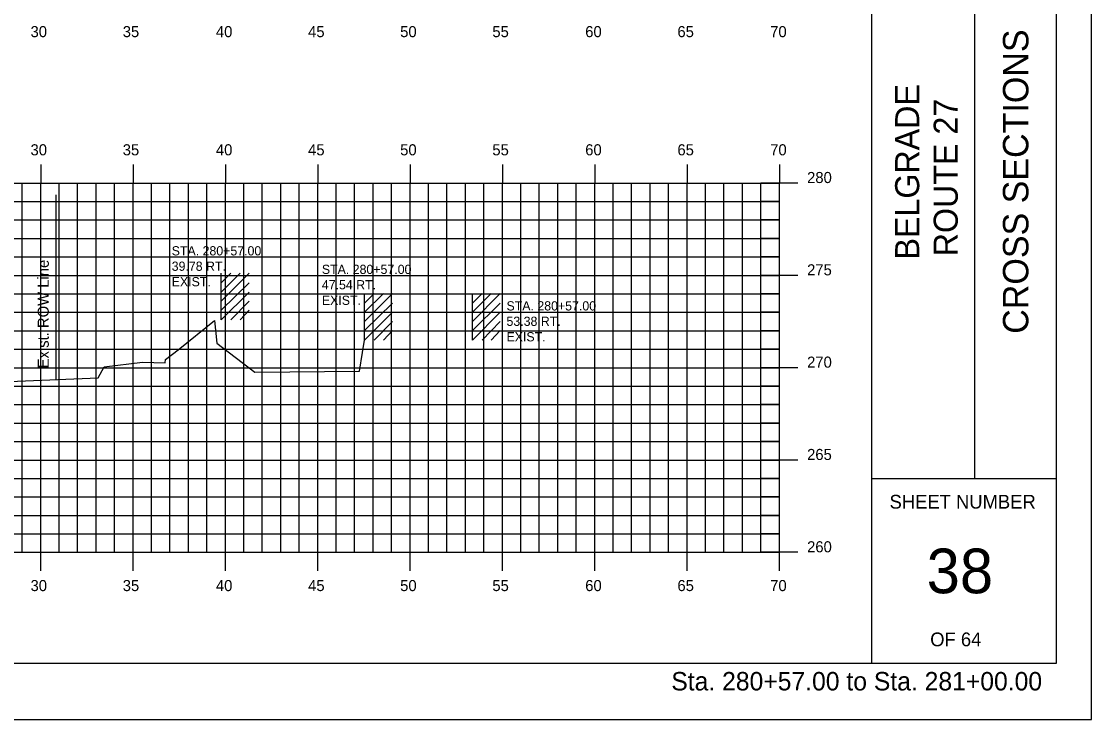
# Model space of a CAD drawing. Extents: x 855344 to 855514, y 366268 to 366378.
# Drawn here: x 855456.1 to 855514, y 366268.2 to 366306 of the extents above; entities that cross this region are included whole.
import ezdxf

# ---------------------------------------------------------------- set-up
doc = ezdxf.new("R2010")
doc.units = 0
for name, color, linetype in [('BORDER', 7, 'Continuous'), ('D_Text_Monospaced', 7, 'Continuous'), ('E_ROW_Line', 7, 'Continuous'), ('H_V ANNOTATION', 7, 'Continuous'), ('HIGHWAY_TITLE', 7, 'Continuous'), ('MAJOR', 7, 'Continuous'), ('MINOR', 7, 'Continuous'), ('PLOT BOUNDARY', 7, 'Continuous'), ('S_Buildings', 7, 'Continuous'), ('S_Buildings_Attachments', 7, 'Continuous'), ('S_Roadway_Centerline', 7, 'Continuous')]:
    doc.layers.add(name, color=color, linetype=linetype)

msp = doc.modelspace()

# ---------------------------------------------------------------- linework, layer by layer
at = {"layer": 'BORDER'}
for p, q in [((855502.11, 366271.236), (855502.11, 366376.239)), ((855512.11, 366271.236), (855512.11, 366376.236)), ((855507.701, 366281.239), (855507.701, 366316.239)), ((855502.11, 366281.239), (855512.11, 366281.239)), ((855352.11, 366271.236), (855512.11, 366271.236))]:
    msp.add_line(p, q, dxfattribs=at)
at = {"layer": 'E_ROW_Line'}
msp.add_line((855457.946, 366286.598), (855457.946, 366296.598), dxfattribs=at)
at = {"layer": 'MAJOR'}
for p, q in [((855457.11, 366298.238), (855457.11, 366297.236)), ((855462.11, 366298.238), (855462.11, 366297.236)), ((855467.11, 366298.238), (855467.11, 366297.236)), ((855472.11, 366298.238), (855472.11, 366297.236)), ((855477.11, 366298.238), (855477.11, 366297.236)), ((855482.11, 366298.238), (855482.11, 366297.236)), ((855487.11, 366298.238), (855487.11, 366297.236)), ((855492.11, 366298.238), (855492.11, 366297.236)), ((855497.11, 366298.238), (855497.11, 366297.236)), ((855357.11, 366297.236), (855497.11, 366297.236)), ((855357.11, 366297.236), (855497.11, 366297.236)), ((855457.11, 366277.236), (855457.11, 366297.236)), ((855462.11, 366277.236), (855462.11, 366297.236)), ((855467.11, 366277.236), (855467.11, 366297.236)), ((855472.11, 366277.236), (855472.11, 366297.236)), ((855477.11, 366277.236), (855477.11, 366297.236)), ((855482.11, 366277.236), (855482.11, 366297.236)), ((855487.11, 366277.236), (855487.11, 366297.236)), ((855492.11, 366277.236), (855492.11, 366297.236)), ((855498.112, 366297.236), (855496.108, 366297.236)), ((855497.11, 366277.236), (855497.11, 366297.236)), ((855497.11, 366277.236), (855497.11, 366297.236)), ((855357.11, 366292.236), (855497.11, 366292.236)), ((855498.112, 366292.236), (855496.108, 366292.236)), ((855357.11, 366287.236), (855497.11, 366287.236)), ((855498.112, 366287.236), (855496.108, 366287.236)), ((855357.11, 366282.236), (855497.11, 366282.236)), ((855498.112, 366282.236), (855496.108, 366282.236)), ((855357.11, 366277.236), (855497.11, 366277.236)), ((855357.11, 366277.236), (855497.11, 366277.236)), ((855457.11, 366276.234), (855457.11, 366277.236)), ((855462.11, 366276.234), (855462.11, 366277.236)), ((855467.11, 366276.234), (855467.11, 366277.236)), ((855472.11, 366276.234), (855472.11, 366277.236)), ((855477.11, 366276.234), (855477.11, 366277.236)), ((855482.11, 366276.234), (855482.11, 366277.236)), ((855487.11, 366276.234), (855487.11, 366277.236)), ((855492.11, 366276.234), (855492.11, 366277.236)), ((855498.112, 366277.236), (855496.108, 366277.236)), ((855497.11, 366276.234), (855497.11, 366277.236))]:
    msp.add_line(p, q, dxfattribs=at)
at = {"layer": 'MINOR'}
for p, q in [((855456.11, 366277.236), (855456.11, 366297.236)), ((855458.11, 366277.236), (855458.11, 366297.236)), ((855459.11, 366277.236), (855459.11, 366297.236)), ((855460.11, 366277.236), (855460.11, 366297.236)), ((855461.11, 366277.236), (855461.11, 366297.236)), ((855463.11, 366277.236), (855463.11, 366297.236)), ((855464.11, 366277.236), (855464.11, 366297.236)), ((855465.11, 366277.236), (855465.11, 366297.236)), ((855466.11, 366277.236), (855466.11, 366297.236)), ((855468.11, 366277.236), (855468.11, 366297.236)), ((855469.11, 366277.236), (855469.11, 366297.236)), ((855470.11, 366277.236), (855470.11, 366297.236)), ((855471.11, 366277.236), (855471.11, 366297.236)), ((855473.11, 366277.236), (855473.11, 366297.236)), ((855474.11, 366277.236), (855474.11, 366297.236)), ((855475.11, 366277.236), (855475.11, 366297.236)), ((855476.11, 366277.236), (855476.11, 366297.236)), ((855478.11, 366277.236), (855478.11, 366297.236)), ((855479.11, 366277.236), (855479.11, 366297.236)), ((855480.11, 366277.236), (855480.11, 366297.236)), ((855481.11, 366277.236), (855481.11, 366297.236)), ((855483.11, 366277.236), (855483.11, 366297.236)), ((855484.11, 366277.236), (855484.11, 366297.236)), ((855485.11, 366277.236), (855485.11, 366297.236)), ((855486.11, 366277.236), (855486.11, 366297.236)), ((855488.11, 366277.236), (855488.11, 366297.236)), ((855489.11, 366277.236), (855489.11, 366297.236)), ((855490.11, 366277.236), (855490.11, 366297.236)), ((855491.11, 366277.236), (855491.11, 366297.236)), ((855493.11, 366277.236), (855493.11, 366297.236)), ((855494.11, 366277.236), (855494.11, 366297.236)), ((855495.11, 366277.236), (855495.11, 366297.236)), ((855496.11, 366277.236), (855496.11, 366297.236)), ((855357.11, 366296.236), (855497.11, 366296.236)), ((855497.11, 366296.236), (855496.108, 366296.236)), ((855357.11, 366295.236), (855497.11, 366295.236)), ((855497.11, 366295.236), (855496.108, 366295.236)), ((855357.11, 366294.236), (855497.11, 366294.236)), ((855497.11, 366294.236), (855496.108, 366294.236)), ((855357.11, 366293.236), (855497.11, 366293.236)), ((855497.11, 366293.236), (855496.108, 366293.236)), ((855357.11, 366291.236), (855497.11, 366291.236)), ((855497.11, 366291.236), (855496.108, 366291.236)), ((855357.11, 366290.236), (855497.11, 366290.236)), ((855497.11, 366290.236), (855496.108, 366290.236)), ((855357.11, 366289.236), (855497.11, 366289.236)), ((855497.11, 366289.236), (855496.108, 366289.236)), ((855357.11, 366288.236), (855497.11, 366288.236)), ((855497.11, 366288.236), (855496.108, 366288.236)), ((855357.11, 366286.236), (855497.11, 366286.236)), ((855497.11, 366286.236), (855496.108, 366286.236)), ((855357.11, 366285.236), (855497.11, 366285.236)), ((855497.11, 366285.236), (855496.108, 366285.236)), ((855357.11, 366284.236), (855497.11, 366284.236)), ((855497.11, 366284.236), (855496.108, 366284.236)), ((855357.11, 366283.236), (855497.11, 366283.236)), ((855497.11, 366283.236), (855496.108, 366283.236)), ((855357.11, 366281.236), (855497.11, 366281.236)), ((855497.11, 366281.236), (855496.108, 366281.236)), ((855357.11, 366280.236), (855497.11, 366280.236)), ((855497.11, 366280.236), (855496.108, 366280.236)), ((855357.11, 366279.236), (855497.11, 366279.236)), ((855497.11, 366279.236), (855496.108, 366279.236)), ((855357.11, 366278.236), (855497.11, 366278.236)), ((855497.11, 366278.236), (855496.108, 366278.236))]:
    msp.add_line(p, q, dxfattribs=at)
at = {"layer": 'PLOT BOUNDARY'}
msp.add_lwpolyline([(855344.016, 366268.177), (855514.016, 366268.177), (855514.016, 366378.177), (855344.016, 366378.177)], close=True, dxfattribs=at)
at = {"layer": 'S_Buildings'}
for p, q in [((855474.65, 366288.725), (855474.65, 366291.251)), ((855474.65, 366289.742), (855476.159, 366291.251)), ((855474.65, 366290.234), (855475.667, 366291.251)), ((855474.65, 366290.726), (855475.175, 366291.251)), ((855480.488, 366288.725), (855480.488, 366291.251)), ((855480.488, 366289.742), (855481.997, 366291.251)), ((855480.488, 366290.234), (855481.505, 366291.251)), ((855480.488, 366290.726), (855481.013, 366291.251)), ((855474.65, 366289.25), (855476.159, 366290.726)), ((855474.65, 366288.725), (855476.159, 366290.234)), ((855480.488, 366289.25), (855481.997, 366290.726)), ((855480.488, 366288.725), (855481.997, 366290.234)), ((855475.175, 366288.725), (855476.159, 366289.742)), ((855481.013, 366288.725), (855481.997, 366289.742)), ((855475.667, 366288.725), (855476.159, 366289.25)), ((855481.505, 366288.725), (855481.997, 366289.25))]:
    msp.add_line(p, q, dxfattribs=at)
at = {"layer": 'S_Buildings_Attachments'}
for p, q in [((855466.888, 366289.822), (855466.888, 366292.348)), ((855466.888, 366290.839), (855468.397, 366292.348)), ((855466.888, 366291.331), (855467.905, 366292.348)), ((855466.888, 366291.823), (855467.413, 366292.348)), ((855466.888, 366290.347), (855468.397, 366291.823)), ((855466.888, 366289.822), (855468.397, 366291.331)), ((855467.413, 366289.822), (855468.397, 366290.839)), ((855467.905, 366289.822), (855468.397, 366290.347))]:
    msp.add_line(p, q, dxfattribs=at)
at = {"layer": 'S_Roadway_Centerline'}
msp.add_lwpolyline([(855448.857, 366286.219), (855460.22, 366286.692), (855460.54, 366287.286), (855462.615, 366287.535), (855463.852, 366287.491), (855463.861, 366287.685), (855464.55, 366288.211), (855466.513, 366289.794), (855466.646, 366288.558), (855468.707, 366286.992), (855474.365, 366287.055), (855474.531, 366288.063), (855474.65, 366288.725)], dxfattribs=at)

# ---------------------------------------------------------------- texts
at = {"layer": 'BORDER'}
for s, height, rotation, p in [('CROSS SECTIONS', 1.37787, 90, (855510.594, 366289.073)), ('SHEET NUMBER', 0.74527, 360, (855503.075, 366279.603)), ('38', 2.4194, 360, (855505.085, 366275.019)), ('OF 64', 0.7453, 360, (855505.277, 366272.149))]:
    msp.add_text(s, height=height, rotation=rotation, dxfattribs=at).set_placement(p)
at = {"layer": 'D_Text_Monospaced'}
for s, height, p in [('STA. 280+57.00', 0.49998, (855464.202, 366293.316)), ('39.78 RT.', 0.5, (855464.202, 366292.482)), ('STA. 280+57.00', 0.49998, (855472.333, 366292.311)), ('EXIST. ', 0.5, (855464.202, 366291.642)), ('47.54 RT.', 0.5, (855472.333, 366291.477)), ('EXIST. ', 0.5, (855472.333, 366290.637)), ('STA. 280+57.00', 0.49998, (855482.332, 366290.334)), ('53.38 RT.', 0.5, (855482.332, 366289.5)), ('EXIST. ', 0.5, (855482.332, 366288.66))]:
    msp.add_text(s, height=height, dxfattribs=at).set_placement(p)
at = {"layer": 'E_ROW_Line'}
msp.add_text('Exist. ROW Line', height=0.6, rotation=90, dxfattribs=at).set_placement((855457.546, 366287.198))
at = {"layer": 'H_V ANNOTATION'}
for s, height, p in [('30', 0.6, (855456.558, 366305.136)), ('35', 0.6, (855461.55, 366305.136)), ('40', 0.6, (855466.596, 366305.136)), ('45', 0.6, (855471.588, 366305.136)), ('50', 0.6, (855476.574, 366305.136)), ('55', 0.6, (855481.566, 366305.136)), ('60', 0.6, (855486.596, 366305.136)), ('65', 0.6, (855491.588, 366305.136)), ('70', 0.6, (855496.612, 366305.136)), ('30', 0.6, (855456.558, 366298.736)), ('35', 0.6, (855461.55, 366298.736)), ('40', 0.6, (855466.596, 366298.736)), ('45', 0.6, (855471.588, 366298.736)), ('50', 0.6, (855476.574, 366298.736)), ('55', 0.6, (855481.566, 366298.736)), ('60', 0.6, (855486.596, 366298.736)), ('65', 0.6, (855491.588, 366298.736)), ('70', 0.6, (855496.612, 366298.736)), ('280', 0.6, (855498.61, 366297.236)), ('275', 0.6, (855498.61, 366292.236)), ('270', 0.6, (855498.61, 366287.236)), ('265', 0.6, (855498.61, 366282.236)), ('260', 0.6, (855498.61, 366277.236)), ('30', 0.6, (855456.558, 366275.136)), ('35', 0.6, (855461.55, 366275.136)), ('40', 0.6, (855466.596, 366275.136)), ('45', 0.6, (855471.588, 366275.136)), ('50', 0.6, (855476.574, 366275.136)), ('55', 0.6, (855481.566, 366275.136)), ('60', 0.6, (855486.596, 366275.136)), ('65', 0.6, (855491.588, 366275.136)), ('70', 0.6, (855496.612, 366275.136)), ('Sta. 280+57.00 to Sta. 281+00.00', 1.0002, (855491.256, 366269.756))]:
    msp.add_text(s, height=height, dxfattribs=at).set_placement(p)
at = {"layer": 'HIGHWAY_TITLE'}
for s, p in [('BELGRADE', (855504.682, 366293.095)), ('ROUTE 27', (855506.769, 366293.269))]:
    msp.add_text(s, height=1.3043, rotation=90, dxfattribs=at).set_placement(p)

doc.saveas('drawing.dxf')
